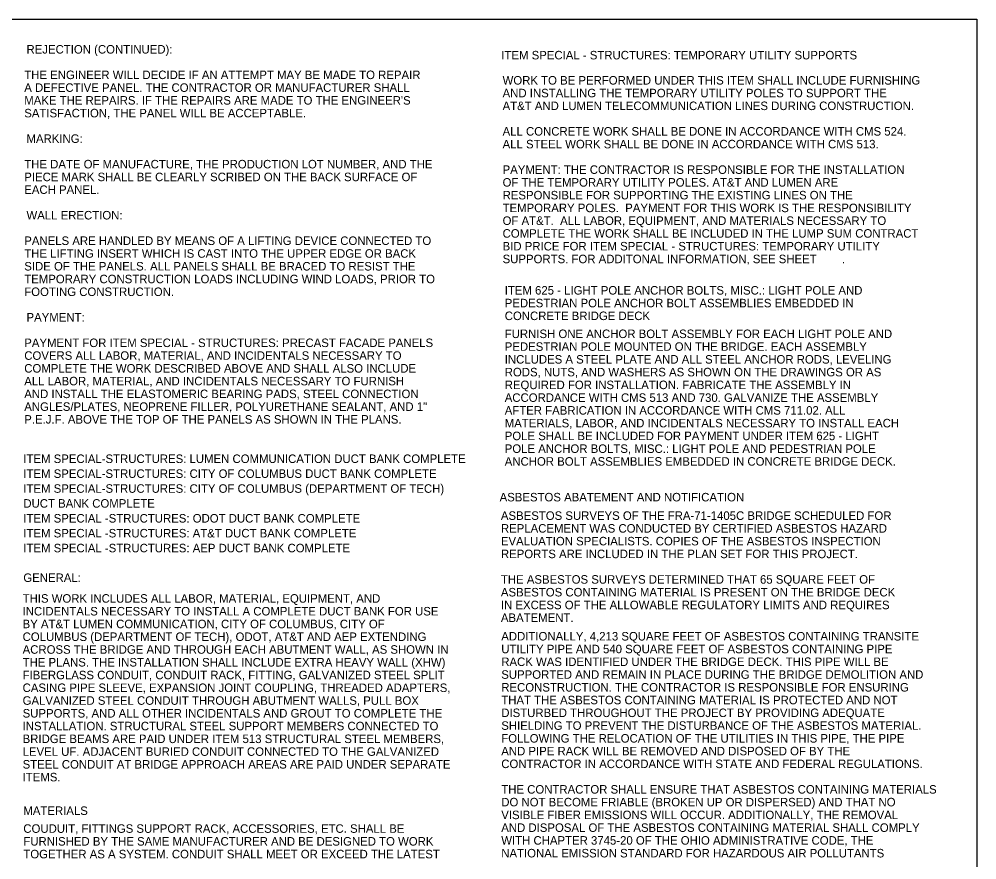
# Model space of a CAD drawing. Extents: x 29 to 1530617, y 1 to 675368.
# Drawn here: x 1530569.92 to 1530585.69, y 675290.52 to 675304.35 of the extents above; entities that cross this region are included whole.
import ezdxf

# ---------------------------------------------------------------- set-up
doc = ezdxf.new("R2010")
doc.units = 0
doc.layers.add('BR_P_Gen_Text', color=7, linetype='Continuous')

msp = doc.modelspace()

# ---------------------------------------------------------------- linework, layer by layer
at = {"layer": 'BR_P_Gen_Text'}
msp.add_lwpolyline([(1530555.188, 675304.353), (1530585.688, 675304.353), (1530585.688, 675283.353), (1530555.188, 675283.353)], close=True, dxfattribs=at)

# ---------------------------------------------------------------- texts
for s, p in [('REJECTION (CONTINUED):', (1530570.045, 675303.787)), ('ITEM SPECIAL - STRUCTURES: TEMPORARY UTILITY SUPPORTS', (1530577.861, 675303.691)), ('THE ENGINEER WILL DECIDE IF AN ATTEMPT MAY BE MADE TO REPAIR ', (1530570.008, 675303.367)), ('WORK TO BE PERFORMED UNDER THIS ITEM SHALL INCLUDE FURNISHING ', (1530577.882, 675303.277)), ('A DEFECTIVE PANEL. THE CONTRACTOR OR MANUFACTURER SHALL ', (1530570.008, 675303.157)), ("MAKE THE REPAIRS. IF THE REPAIRS ARE MADE TO THE ENGINEER'S ", (1530570.008, 675302.947)), ('AND INSTALLING THE TEMPORARY UTILITY POLES TO SUPPORT THE ', (1530577.882, 675303.067)), ('AT&T AND LUMEN TELECOMMUNICATION LINES DURING CONSTRUCTION.  ', (1530577.882, 675302.857)), ('SATISFACTION, THE PANEL WILL BE ACCEPTABLE.', (1530570.008, 675302.737)), ('MARKING:', (1530570.045, 675302.317)), ('ALL CONCRETE WORK SHALL BE DONE IN ACCORDANCE WITH CMS 524.  ', (1530577.882, 675302.437)), ('ALL STEEL WORK SHALL BE DONE IN ACCORDANCE WITH CMS 513. ', (1530577.882, 675302.227)), ('THE DATE OF MANUFACTURE, THE PRODUCTION LOT NUMBER, AND THE ', (1530570.008, 675301.897)), ('PIECE MARK SHALL BE CLEARLY SCRIBED ON THE BACK SURFACE OF ', (1530570.008, 675301.687)), ('PAYMENT: THE CONTRACTOR IS RESPONSIBLE FOR THE INSTALLATION ', (1530577.882, 675301.807)), ('OF THE TEMPORARY UTILITY POLES. AT&T AND LUMEN ARE ', (1530577.882, 675301.597)), ('EACH PANEL.', (1530570.008, 675301.477)), ('RESPONSIBLE FOR SUPPORTING THE EXISTING LINES ON THE ', (1530577.882, 675301.387)), ('WALL ERECTION:', (1530570.045, 675301.057)), ('TEMPORARY POLES.  PAYMENT FOR THIS WORK IS THE RESPONSIBILITY ', (1530577.882, 675301.177)), ('OF AT&T.  ALL LABOR, EQUIPMENT, AND MATERIALS NECESSARY TO ', (1530577.882, 675300.967)), ('COMPLETE THE WORK SHALL BE INCLUDED IN THE LUMP SUM CONTRACT ', (1530577.882, 675300.757)), ('PANELS ARE HANDLED BY MEANS OF A LIFTING DEVICE CONNECTED TO ', (1530570.008, 675300.637)), ('THE LIFTING INSERT WHICH IS CAST INTO THE UPPER EDGE OR BACK ', (1530570.008, 675300.427)), ('BID PRICE FOR ITEM SPECIAL - STRUCTURES: TEMPORARY UTILITY ', (1530577.882, 675300.547)), ('SUPPORTS. FOR ADDITONAL INFORMATION, SEE SHEET        .', (1530577.882, 675300.337)), ('SIDE OF THE PANELS. ALL PANELS SHALL BE BRACED TO RESIST THE ', (1530570.008, 675300.217)), ('TEMPORARY CONSTRUCTION LOADS INCLUDING WIND LOADS, PRIOR TO ', (1530570.008, 675300.007)), ('FOOTING CONSTRUCTION.', (1530570.008, 675299.797)), ('ITEM 625 - LIGHT POLE ANCHOR BOLTS, MISC.: LIGHT POLE AND ', (1530577.917, 675299.821)), ('PEDESTRIAN POLE ANCHOR BOLT ASSEMBLIES EMBEDDED IN ', (1530577.917, 675299.611)), ('PAYMENT:', (1530570.045, 675299.377)), ('CONCRETE BRIDGE DECK', (1530577.917, 675299.401)), ('FURNISH ONE ANCHOR BOLT ASSEMBLY FOR EACH LIGHT POLE AND ', (1530577.917, 675299.105)), ('PAYMENT FOR ITEM SPECIAL - STRUCTURES: PRECAST FACADE PANELS ', (1530570.008, 675298.957)), ('PEDESTRIAN POLE MOUNTED ON THE BRIDGE. EACH ASSEMBLY ', (1530577.917, 675298.895)), ('COVERS ALL LABOR, MATERIAL, AND INCIDENTALS NECESSARY TO ', (1530570.008, 675298.747)), ('INCLUDES A STEEL PLATE AND ALL STEEL ANCHOR RODS, LEVELING ', (1530577.917, 675298.685)), ('COMPLETE THE WORK DESCRIBED ABOVE AND SHALL ALSO INCLUDE ', (1530570.008, 675298.537)), ('RODS, NUTS, AND WASHERS AS SHOWN ON THE DRAWINGS OR AS ', (1530577.917, 675298.475)), ('ALL LABOR, MATERIAL, AND INCIDENTALS NECESSARY TO FURNISH ', (1530570.008, 675298.327)), ('REQUIRED FOR INSTALLATION. FABRICATE THE ASSEMBLY IN ', (1530577.917, 675298.265)), ('AND INSTALL THE ELASTOMERIC BEARING PADS, STEEL CONNECTION ', (1530570.008, 675298.117)), ('ACCORDANCE WITH CMS 513 AND 730. GALVANIZE THE ASSEMBLY ', (1530577.917, 675298.055)), ('ANGLES/PLATES, NEOPRENE FILLER, POLYURETHANE SEALANT, AND 1" ', (1530570.008, 675297.907)), ('AFTER FABRICATION IN ACCORDANCE WITH CMS 711.02. ALL ', (1530577.917, 675297.845)), ('P.E.J.F. ABOVE THE TOP OF THE PANELS AS SHOWN IN THE PLANS.', (1530570.008, 675297.697)), ('MATERIALS, LABOR, AND INCIDENTALS NECESSARY TO INSTALL EACH ', (1530577.917, 675297.635)), ('POLE SHALL BE INCLUDED FOR PAYMENT UNDER ITEM 625 - LIGHT ', (1530577.917, 675297.425)), ('POLE ANCHOR BOLTS, MISC.: LIGHT POLE AND PEDESTRIAN POLE ', (1530577.917, 675297.215)), ('ITEM SPECIAL-STRUCTURES: LUMEN COMMUNICATION DUCT BANK COMPLETE', (1530569.993, 675297.049)), ('ANCHOR BOLT ASSEMBLIES EMBEDDED IN CONCRETE BRIDGE DECK.', (1530577.917, 675297.005)), ('ITEM SPECIAL-STRUCTURES: CITY OF COLUMBUS DUCT BANK COMPLETE ', (1530569.993, 675296.804)), ('ITEM SPECIAL-STRUCTURES: CITY OF COLUMBUS (DEPARTMENT OF TECH) ', (1530569.993, 675296.559)), ('ASBESTOS ABATEMENT AND NOTIFICATION', (1530577.833, 675296.417)), ('DUCT BANK COMPLETE', (1530569.993, 675296.314)), ('ITEM SPECIAL -STRUCTURES: ODOT DUCT BANK COMPLETE ', (1530569.993, 675296.069)), ('ASBESTOS SURVEYS OF THE FRA-71-1405C BRIDGE SCHEDULED FOR ', (1530577.854, 675296.113)), ('REPLACEMENT WAS CONDUCTED BY CERTIFIED ASBESTOS HAZARD ', (1530577.854, 675295.903)), ('ITEM SPECIAL -STRUCTURES: AT&T DUCT BANK COMPLETE ', (1530569.993, 675295.824)), ('EVALUATION SPECIALISTS. COPIES OF THE ASBESTOS INSPECTION ', (1530577.854, 675295.693)), ('ITEM SPECIAL -STRUCTURES: AEP DUCT BANK COMPLETE ', (1530569.993, 675295.579)), ('REPORTS ARE INCLUDED IN THE PLAN SET FOR THIS PROJECT. ', (1530577.854, 675295.483)), ('GENERAL:', (1530569.993, 675295.091)), ('THE ASBESTOS SURVEYS DETERMINED THAT 65 SQUARE FEET OF ', (1530577.854, 675295.063)), ('THIS WORK INCLUDES ALL LABOR, MATERIAL, EQUIPMENT, AND ', (1530569.981, 675294.75)), ('ASBESTOS CONTAINING MATERIAL IS PRESENT ON THE BRIDGE DECK ', (1530577.854, 675294.853)), ('IN EXCESS OF THE ALLOWABLE REGULATORY LIMITS AND REQUIRES ', (1530577.854, 675294.643)), ('INCIDENTALS NECESSARY TO INSTALL A COMPLETE DUCT BANK FOR USE ', (1530569.981, 675294.54)), ('ABATEMENT. ', (1530577.854, 675294.433)), ('BY AT&T LUMEN COMMUNICATION, CITY OF COLUMBUS, CITY OF ', (1530569.981, 675294.33)), ('COLUMBUS (DEPARTMENT OF TECH), ODOT, AT&T AND AEP EXTENDING ', (1530569.981, 675294.12)), ('ADDITIONALLY, 4,213 SQUARE FEET OF ASBESTOS CONTAINING TRANSITE ', (1530577.86, 675294.128)), ('ACROSS THE BRIDGE AND THROUGH EACH ABUTMENT WALL, AS SHOWN IN ', (1530569.981, 675293.91)), ('UTILITY PIPE AND 540 SQUARE FEET OF ASBESTOS CONTAINING PIPE ', (1530577.86, 675293.918)), ('THE PLANS. THE INSTALLATION SHALL INCLUDE EXTRA HEAVY WALL (XHW) ', (1530569.981, 675293.7)), ('RACK WAS IDENTIFIED UNDER THE BRIDGE DECK. THIS PIPE WILL BE ', (1530577.86, 675293.708)), ('FIBERGLASS CONDUIT, CONDUIT RACK, FITTING, GALVANIZED STEEL SPLIT ', (1530569.981, 675293.49)), ('SUPPORTED AND REMAIN IN PLACE DURING THE BRIDGE DEMOLITION AND ', (1530577.86, 675293.498)), ('CASING PIPE SLEEVE, EXPANSION JOINT COUPLING, THREADED ADAPTERS, ', (1530569.981, 675293.28)), ('RECONSTRUCTION. THE CONTRACTOR IS RESPONSIBLE FOR ENSURING ', (1530577.86, 675293.288)), ('GALVANIZED STEEL CONDUIT THROUGH ABUTMENT WALLS, PULL BOX ', (1530569.981, 675293.07)), ('THAT THE ASBESTOS CONTAINING MATERIAL IS PROTECTED AND NOT ', (1530577.86, 675293.078)), ('SUPPORTS, AND ALL OTHER INCIDENTALS AND GROUT TO COMPLETE THE ', (1530569.981, 675292.86)), ('DISTURBED THROUGHOUT THE PROJECT BY PROVIDING ADEQUATE ', (1530577.86, 675292.868)), ('INSTALLATION. STRUCTURAL STEEL SUPPORT MEMBERS CONNECTED TO ', (1530569.981, 675292.65)), ('SHIELDING TO PREVENT THE DISTURBANCE OF THE ASBESTOS MATERIAL. ', (1530577.86, 675292.658)), ('BRIDGE BEAMS ARE PAID UNDER ITEM 513 STRUCTURAL STEEL MEMBERS, ', (1530569.981, 675292.44)), ('FOLLOWING THE RELOCATION OF THE UTILITIES IN THIS PIPE, THE PIPE ', (1530577.86, 675292.448)), ('LEVEL UF. ADJACENT BURIED CONDUIT CONNECTED TO THE GALVANIZED ', (1530569.981, 675292.23)), ('AND PIPE RACK WILL BE REMOVED AND DISPOSED OF BY THE ', (1530577.86, 675292.238)), ('STEEL CONDUIT AT BRIDGE APPROACH AREAS ARE PAID UNDER SEPARATE ', (1530569.981, 675292.02)), ('CONTRACTOR IN ACCORDANCE WITH STATE AND FEDERAL REGULATIONS.', (1530577.86, 675292.028)), ('ITEMS.', (1530569.981, 675291.81)), ('THE CONTRACTOR SHALL ENSURE THAT ASBESTOS CONTAINING MATERIALS ', (1530577.86, 675291.608)), ('DO NOT BECOME FRIABLE (BROKEN UP OR DISPERSED) AND THAT NO ', (1530577.86, 675291.398)), ('MATERIALS', (1530569.993, 675291.257)), ('VISIBLE FIBER EMISSIONS WILL OCCUR. ADDITIONALLY, THE REMOVAL ', (1530577.86, 675291.188)), ('COUDUIT, FITTINGS SUPPORT RACK, ACCESSORIES, ETC. SHALL BE ', (1530569.993, 675290.963)), ('AND DISPOSAL OF THE ASBESTOS CONTAINING MATERIAL SHALL COMPLY ', (1530577.86, 675290.978)), ('FURNISHED BY THE SAME MANUFACTURER AND BE DESIGNED TO WORK ', (1530569.993, 675290.753)), ('WITH CHAPTER 3745-20 OF THE OHIO ADMINISTRATIVE CODE, THE ', (1530577.86, 675290.768)), ('TOGETHER AS A SYSTEM. CONDUIT SHALL MEET OR EXCEED THE LATEST ', (1530569.993, 675290.543)), ('NATIONAL EMISSION STANDARD FOR HAZARDOUS AIR POLLUTANTS ', (1530577.86, 675290.558))]:
    msp.add_text(s, height=0.14, dxfattribs=at).set_placement(p)

doc.saveas('drawing.dxf')
